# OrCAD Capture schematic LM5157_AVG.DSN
size Custom; title: LM5157x 2.2-MHz Wide VIN Boost/Sepic/Flyback Converter with; rev: 1.0; note: Datasheet: SNVSBK7    EVM: NA; note: Synchronous Step Down Converter
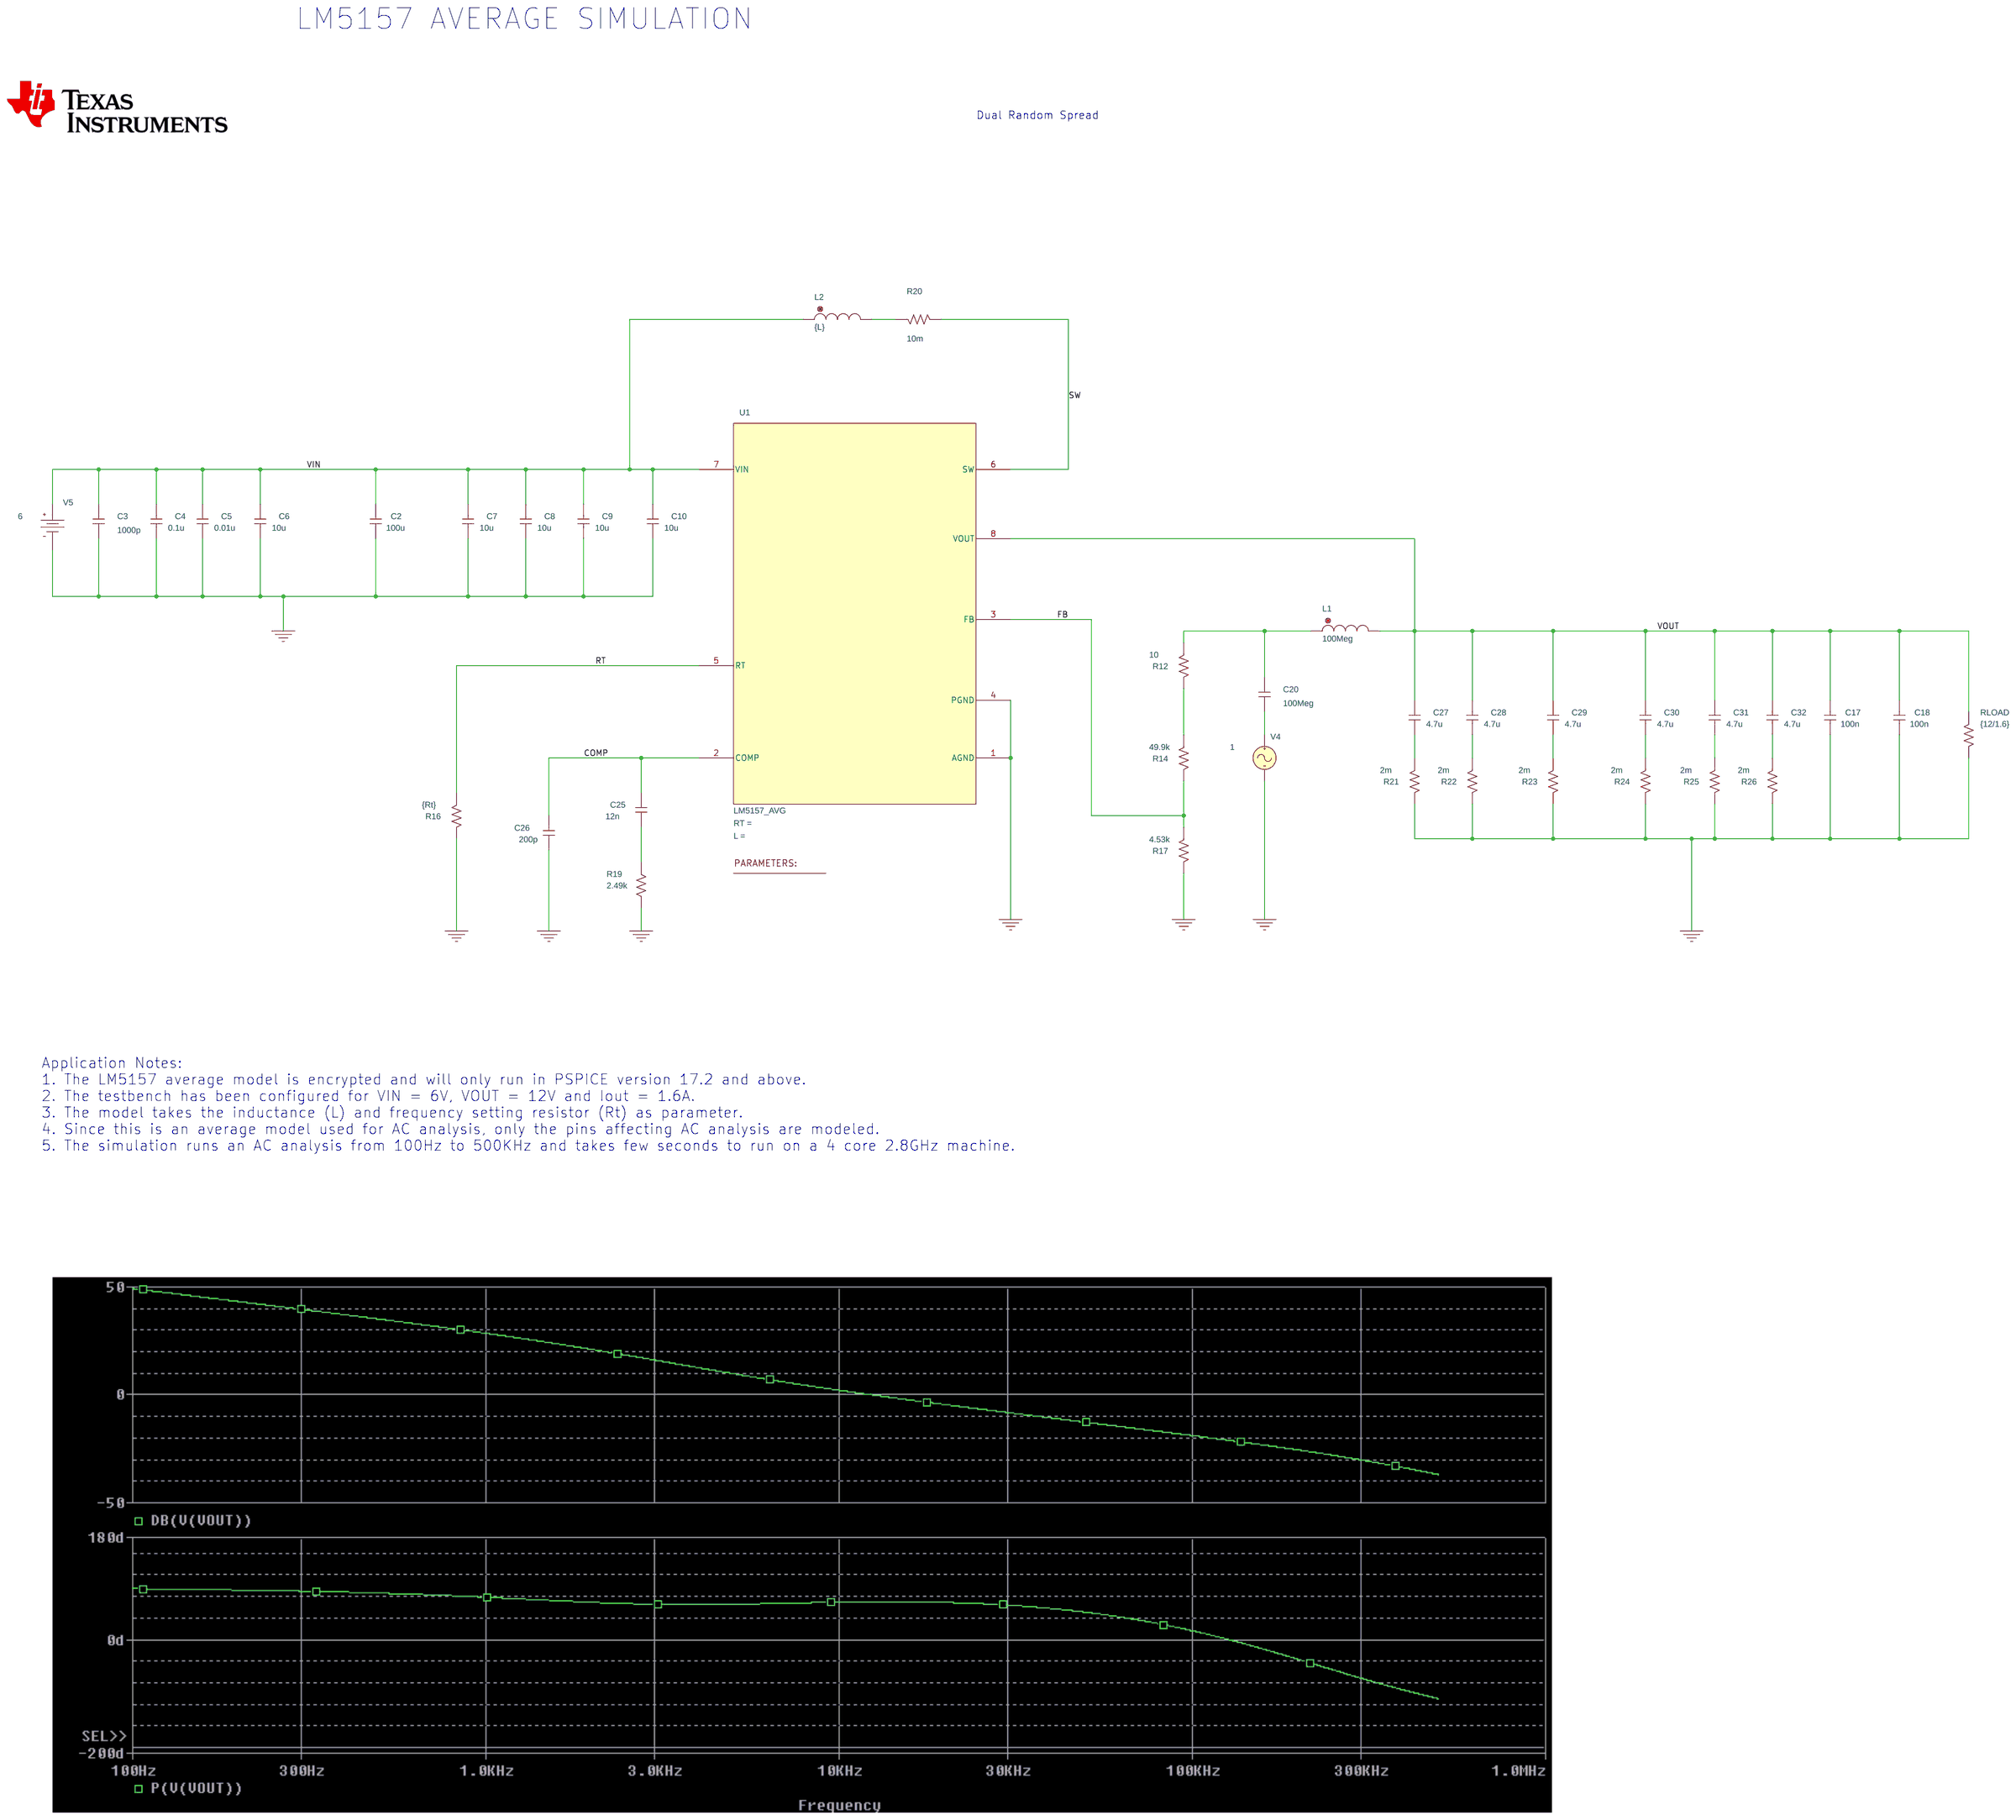
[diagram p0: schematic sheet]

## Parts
1  PARAM
C2  100u  [RAD/CK05]
C3  1000p  [RAD/CK05]
C4  0.1u  [RAD/CK05]
C5  0.01u  [RAD/CK05]
C6  10u  [RAD/CK05]
C7  10u  [RAD/CK05]
C8  10u  [RAD/CK05]
C9  10u  [RAD/CK05]
C10  10u  [RAD/CK05]
C17  100n  [RAD/CK05]
C18  100n  [RAD/CK05]
C20  100Meg  [RAD/CK05]
C25  12n  [RAD/CK05]
C26  200p  [RAD/CK05]
C27  4.7u  [RAD/CK05]
C28  4.7u  [RAD/CK05]
C29  4.7u  [RAD/CK05]
C30  4.7u  [RAD/CK05]
C31  4.7u  [RAD/CK05]
C32  4.7u  [RAD/CK05]
L1  100Meg  [DISC/.350x.175/LS.200x.100/.034]
L2  {L}  [DISC/.350x.175/LS.200x.100/.034]
R12  10  [AX/RC05]
R14  49.9k  [AX/RC05]
R16  {Rt}  [AX/RC05]
R17  4.53k  [AX/RC05]
R19  2.49k  [AX/RC05]
R20  10m  [AX/RC05]
R21  2m  [AX/RC05]
R22  2m  [AX/RC05]
R23  2m  [AX/RC05]
R24  2m  [AX/RC05]
R25  2m  [AX/RC05]
R26  2m  [AX/RC05]
RLOAD  {12/1.6}  [AX/RC05]
U1  LM5157_AVG
V4  VAC
V5  VDC

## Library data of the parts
1 = PARAM: L: 1.5u; R4: 1u; R5: 100; R6: 0.008; Rt: 9.53k
C2-C10 C17 C18 C20 C25-C32 = C
L1 L2 = L
R12 R14 R16 R17 R19-R26 RLOAD = R
U1 = LM5157_AVG
V4 = VAC: ACMAG: 1; ACPHASE: 0
V5 = VDC: DC: 6

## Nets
VIN: C2.1 C3.1 C4.1 C5.1 C6.1 C7.1 C8.1 C9.1 C10.1 L2.1 U1.7(VIN) V5.0(+)
0: C2.2 C3.2 C4.2 C5.2 C6.2 C7.2 C8.2 C9.2 C10.2 C17.2 C18.2 C26.2 R16.2 R17.2 R19.2 R21.2 R22.2 R23.2 R24.2 R25.2 R26.2 RLOAD.2 U1.1(AGND) U1.4(PGND) V4.2(-) V5.1(-)
COMP: C25.1 C26.1 U1.2(COMP)
FB: R14.2 R17.1 U1.3(FB)
RT: R16.1 U1.5(RT)
SW: R20.2 U1.6(SW)
VOUT: C17.1 C18.1 C27.1 C28.1 C29.1 C30.1 C31.1 C32.1 L1.2 RLOAD.1 U1.8(VOUT)
N299689: C20.2 V4.1(+)
N302312: C25.2 R19.1
N304851: C20.1 L1.1 R12.1
N16777327: L2.2 R20.1
N16777661: C27.2 R21.1
N16777802: C28.2 R22.1
N16777909: C29.2 R23.1
N16778020: C30.2 R24.1
N16778135: C31.2 R25.1
N16778253: C32.2 R26.1
N16829923: R12.2 R14.1

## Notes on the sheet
- LM5157 AVERAGE SIMULATION
- Dual Random Spread
- Application Notes:
  1. The LM5157 average model is encrypted and will only run in PSPICE version 17.2 and above.
  2. The testbench has been configured for VIN = 6V, VOUT = 12V and Iout = 1.6A.
  3. The model takes the inductance (L) and frequency setting resistor (Rt) as parameter.
  4. Since this is an average model used for AC analysis, only the pins affecting AC analysis are modeled.
  5. The simulation runs an AC analysis from 100Hz to 500KHz and takes few seconds to run on a 4 core 2.8GHz machine.
